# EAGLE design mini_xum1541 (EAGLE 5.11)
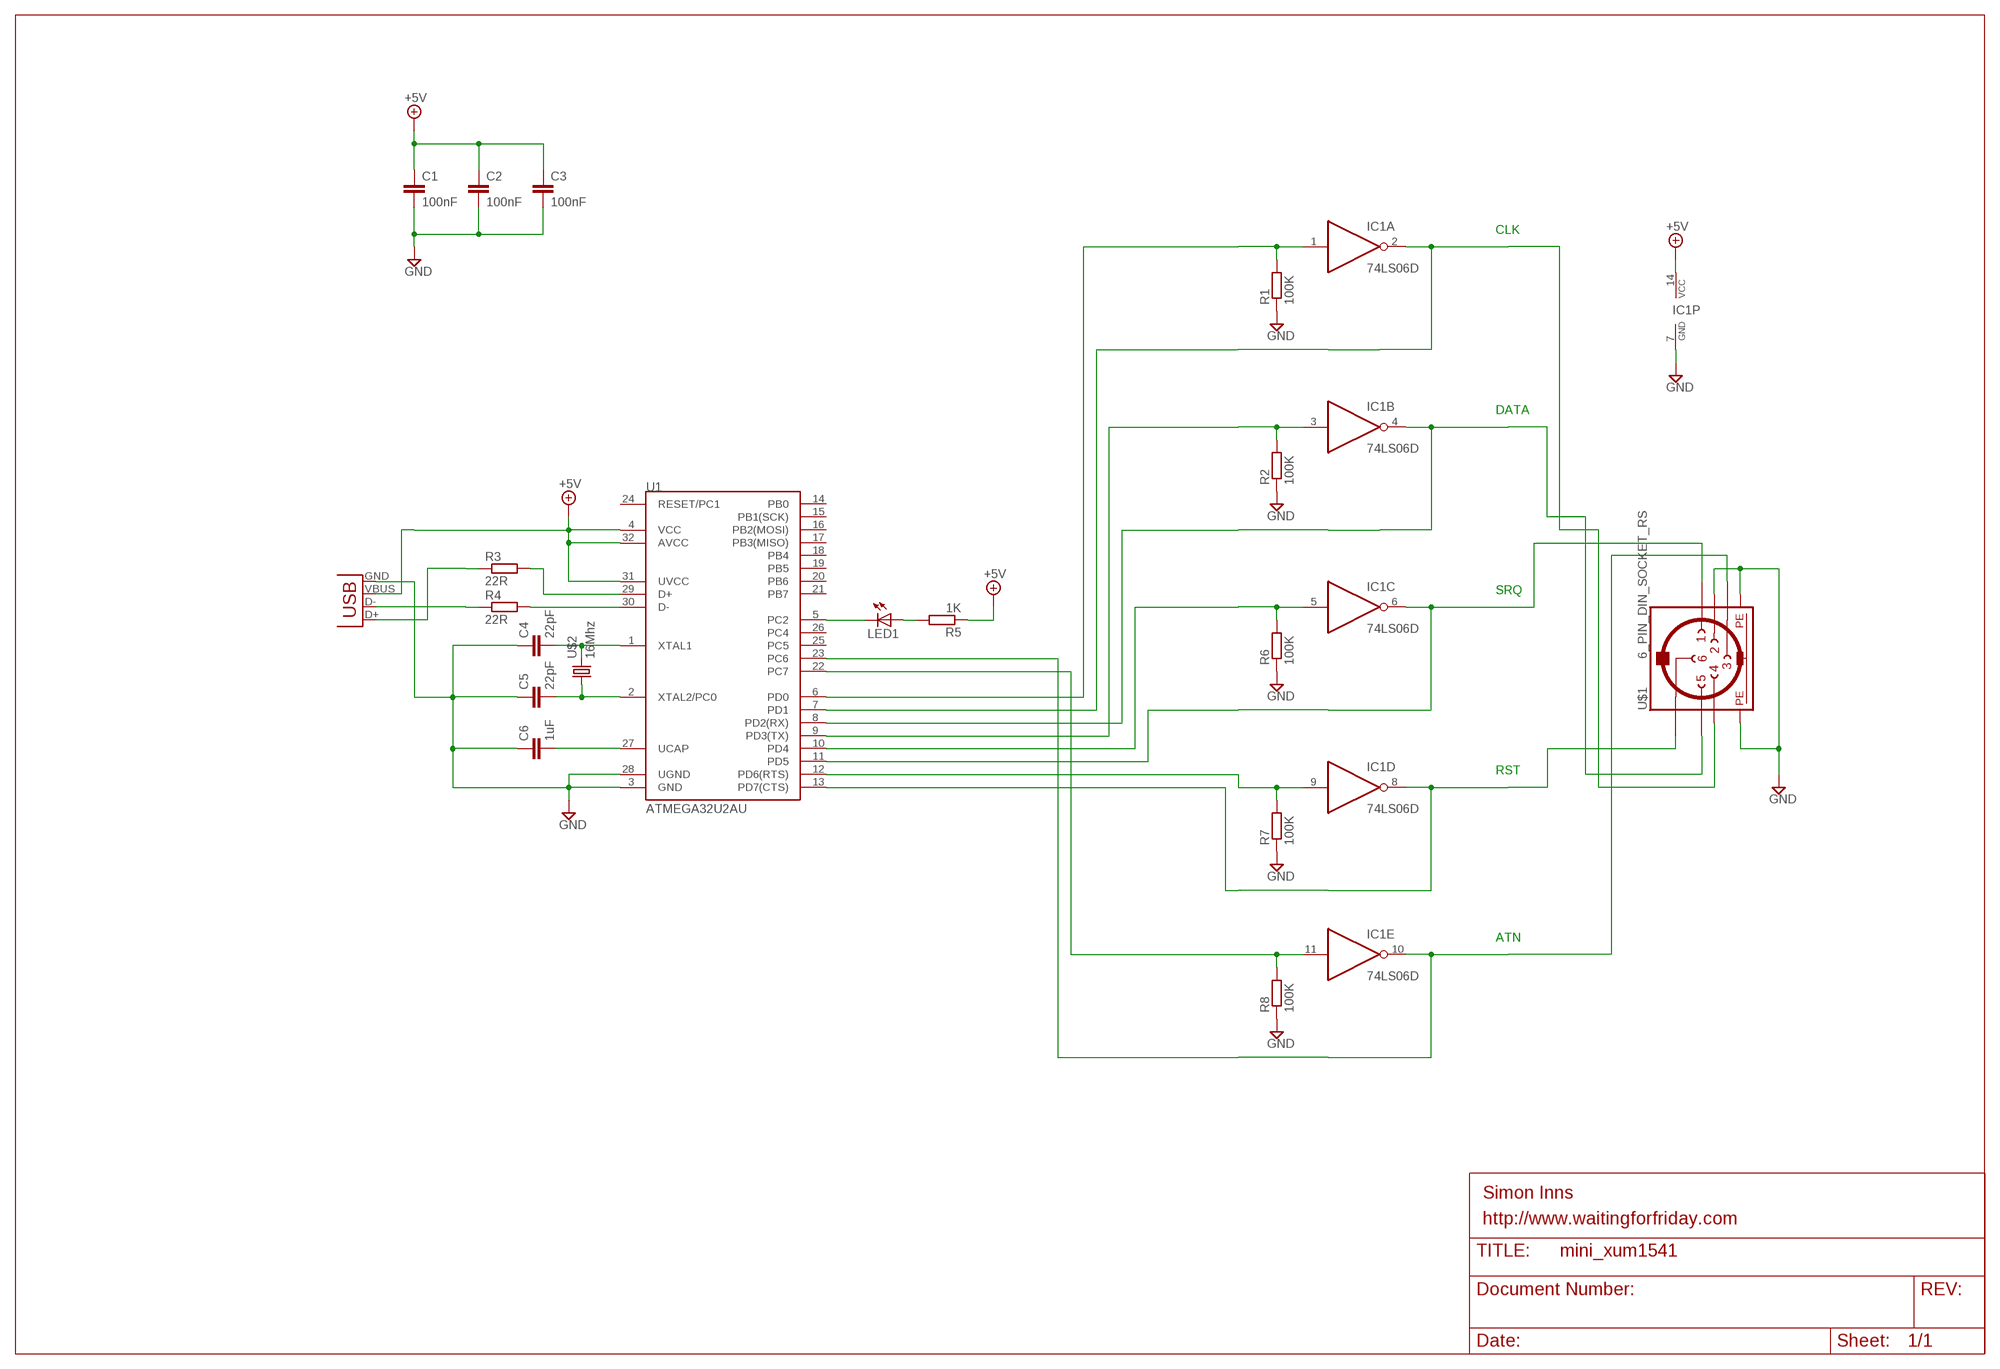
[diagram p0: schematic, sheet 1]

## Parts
C1  100nF  C-EUC0805  [C0805]
C2  100nF  C-EUC0805  [C0805]
C3  100nF  C-EUC0805  [C0805]
C4  22pF  C-EUC0805  [C0805]
C5  22pF  C-EUC0805  [C0805]
C6  1uF  C-EUC0805  [C0805]
IC1  74LS06D  [SO14]
LED1  LED3MM  [LED3MM]
R1  100K  R-EU_M1206  [M1206]
R2  100K  R-EU_M1206  [M1206]
R3  22R  R-EU_M1206  [M1206]
R4  22R  R-EU_M1206  [M1206]
R5  1K  R-EU_M1206  [M1206]
R6  100K  R-EU_M1206  [M1206]
R7  100K  R-EU_M1206  [M1206]
R8  100K  R-EU_M1206  [M1206]
U1  ATMEGA32U2AU  ATMEGA8U2AU  [TQFP32-08]
U$1  6_PIN_DIN_SOCKET_RS  [MAB6H_RS]
U$2  16Mhz  CRYSTAL_SMD3X5MM  [CRYSTAL_SMD_3X5MM]
X1  USBPTH  [USB-B-PTH]

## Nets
+5V: C1.1 C2.1 C3.1 IC1.14(P:VCC) R5.1 U1.4(VCC) U1.31(UVCC) U1.32(AVCC) X1.VBUS
GND: C1.2 C2.2 C3.2 C4.1 C5.1 C6.1 IC1.7(P:GND) R1.1 R2.1 R6.1 R7.1 R8.1 U1.3(GND) U1.28(UGND) U$1.2 U$1.PE U$1.PE@(PE) X1.GND
N$1: IC1.1(A:I) R1.2 U1.6(PD0)
N$3: IC1.2(A:O) U1.7(PD1) U$1.4
N$4: IC1.3(B:I) R2.2 U1.9(PD3(TX))
N$6: IC1.4(B:O) U1.8(PD2(RX)) U$1.5
N$7: IC1.5(C:I) R6.2 U1.10(PD4)
N$9: IC1.6(C:O) U1.11(PD5) U$1.1
N$10: IC1.9(D:I) R7.2 U1.12(PD6(RTS))
N$12: IC1.8(D:O) U1.13(PD7(CTS)) U$1.6
N$13: IC1.11(E:I) R8.2 U1.22(PC7)
N$15: IC1.10(E:O) U1.23(PC6) U$1.3
N$20: C6.2 U1.27(UCAP)
N$21: C5.2 U1.2(XTAL2/PC0) U$2.1
N$22: C4.2 U1.1(XTAL1) U$2.2
N$23: R4.1 X1.D-
N$24: R4.2 U1.30(D-)
N$25: R3.1 X1.D+
N$26: R3.2 U1.29(D+)
N$32: LED1.K(C) U1.5(PC2)
N$33: LED1.A R5.2
Unconnected: IC1.12(F:O) IC1.13(F:I) U1.14(PB0) U1.15(PB1(SCK)) U1.16(PB2(MOSI)) U1.17(PB3(MISO)) U1.18(PB4) U1.19(PB5) U1.20(PB6) U1.21(PB7) U1.24(RESET/PC1) U1.25(PC5) U1.26(PC4)

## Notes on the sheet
- CLK
- DATA
- SRQ
- RST
- ATN
- Simon Inns
- http://www.waitingforfriday.com

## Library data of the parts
C1-C6 = rcl:C-EU: CAPACITOR, European symbol
IC1 = 74xx-eu:74*06: Hex INVERTER, open collector high-voltage output
LED1 = led:LED: LED
R1-R8 = rcl:R-EU_: RESISTOR, European symbol
U1 = SparkFun:ATMEGA8U2: Atmel 8-bit Microcontroller with 8/16/32K Bystes of ISP Flash and USB Controller. ATmega8U2, ATmega16U2, and ATmega32U2
U$1 = simonslbr:6_PIN_DIN_SOCKET_RS: 6 PIN DIN Socket for PCB mounting RS Components part number 491033
U$2 = simonslbr:CRYSTAL_SMD3X5MM: SMD Crystal 3.2mm X 5mm dual pads
X1 = SparkFun:USB: USB Connectors USB-B-PTH is fully proven SKU : PRT-00139 USB-miniB is fully proven SKU : PRT-00587 USB-A-PCB is untested. USB-A-H is throughly reviewed, but untested. Spark Fun Electronics SKU : PRT-00437 USB-B-SMT is throughly reviewed, but untested. Needs silkscreen touching up. USB-A-S has not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

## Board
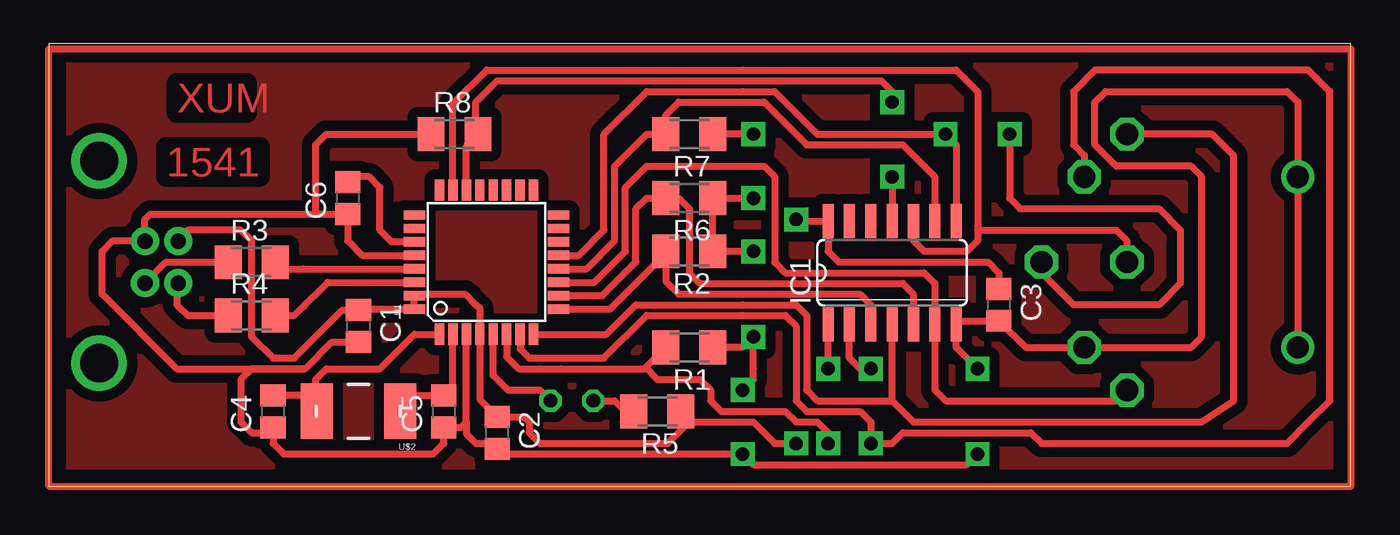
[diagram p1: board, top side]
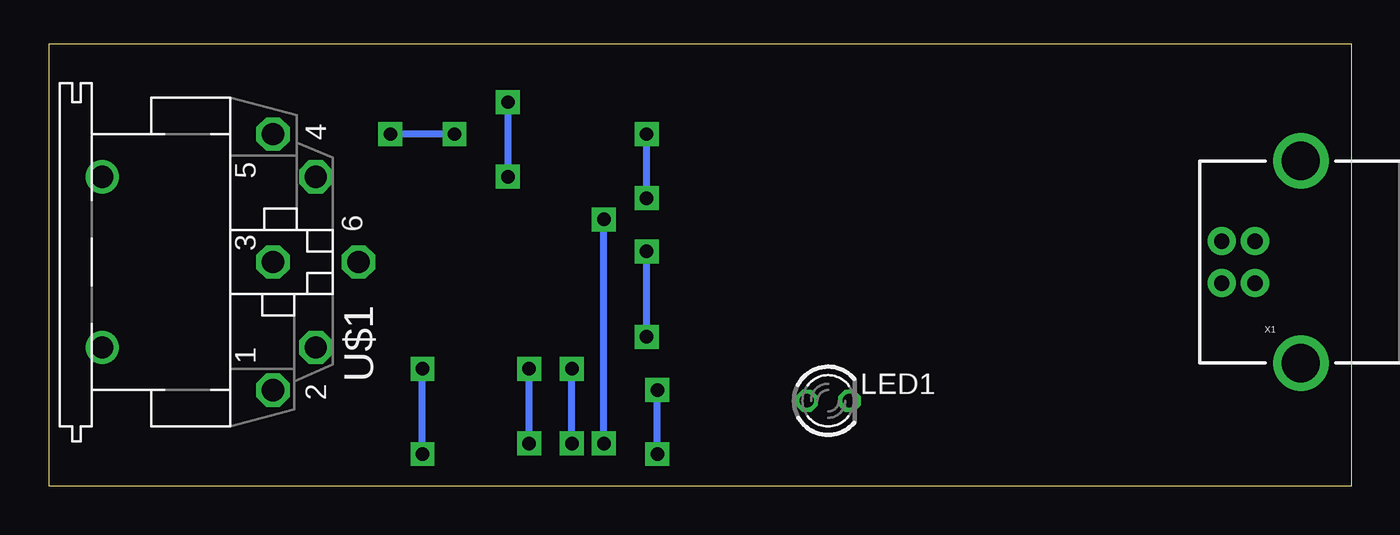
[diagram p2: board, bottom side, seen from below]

Size 77.45 x 26.34 mm. Coordinates in mm from the lower left corner, seen from the top.
Outline: 0,0 77.45,0 77.45,26.34 0,26.34 0,0
Copper layers (1*16): Top 0.035mm / dielectric 1.5mm / Bottom 0.035mm
Design rules "default": minimum track width 10mil, minimum drill 24mil, track to track 8mil, track to pad 8mil, pad to pad 8mil, via to via 8mil, smd to smd 8mil, copper to edge 40mil, drill to drill 8mil, minimum pad ring 10mil, minimum via ring 8mil, stop-mask expansion 4mil, vias tented up to drill 0mil, thermal gap 10mil

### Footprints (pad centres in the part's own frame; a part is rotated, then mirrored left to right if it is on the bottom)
C0805 = smd 1.3 x 1.5: 1 -0.95,0; 2 0.95,0
SO14 = smd 0.66 x 2.032: 1 -3.81,-3.073; 2 -2.54,-3.073; 3 -1.27,-3.073; 4 0,-3.073; 5 1.27,-3.073; 6 2.54,-3.073; 7 3.81,-3.073; 8 3.81,3.073; 9 2.54,3.073; 10 1.27,3.073; 11 0,3.073; 12 -1.27,3.073; 13 -2.54,3.073; 14 -3.81,3.073
LED3MM = drill 0.813 octagon: A -1.27,0; K 1.27,0
M1206 = smd 1.6 x 2: 1 -1.4,0; 2 1.4,0
TQFP32-08 = smd 1.27 x 0.559: 1 -4.293,2.8; 2 -4.293,2; 3 -4.293,1.2; 4 -4.293,0.4; 5 -4.293,-0.4; 6 -4.293,-1.2; 7 -4.293,-2; 8 -4.293,-2.8; 17 4.293,-2.8; 18 4.293,-2; 19 4.293,-1.2; 20 4.293,-0.4; 21 4.293,0.4; 22 4.293,1.2; 23 4.293,2; 24 4.293,2.8 | smd 0.559 x 1.27: 9 -2.8,-4.293; 10 -2,-4.293; 11 -1.2,-4.293; 12 -0.4,-4.293; 13 0.4,-4.293; 14 1.2,-4.293; 15 2,-4.293; 16 2.8,-4.293; 25 2.8,4.293; 26 2,4.293; 27 1.2,4.293; 28 0.4,4.293; 29 -0.4,4.293; 30 -1.2,4.293; 31 -2,4.293; 32 -2.8,4.293
MAB6H_RS = drill 1.321 octagon: 1 7.62,5.08; 2 5.08,7.62; 3 0,5.08; 4 -5.08,7.62; 5 -7.62,5.08; 6 0,10.16 | drill 1.321 round: PE -5.08,-5.08; PE@ 5.08,-5.08
CRYSTAL_SMD_3X5MM = smd 1.9 x 3.302: 1 -2.485,-0.007; 2 2.468,-0.007
USB-B-PTH = drill 0.914 pad 1.676 round: D+ 0,1.25; D- 1.981,1.25; GND 0,-1.25; VBUS 1.981,-1.25 | drill 2.286 round: S1 -2.718,-6.02; S2 -2.718,6.02

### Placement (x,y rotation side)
C1  18.41,9.53 270 top
C2  26.67,3.17 270 top
C3  56.52,10.79 270 top
C4  13.34,4.45 90 top
C5  23.5,4.45 90 top
C6  17.78,17.14 90 top
IC1  50.16,12.7 0 top
LED1  31.11,5.08 0 bottom
R1  38.1,8.26 180 top
R2  38.1,13.97 180 top
R3  12.06,13.34 0 top
R4  12.06,10.16 0 top
R5  36.2,4.45 180 top
R6  38.1,17.14 180 top
R7  38.1,20.95 180 top
R8  24.13,20.95 0 top
U1  ATMEGA16U2AU  [TQFP32-08]  26.04,13.34 90 top
U$1  69.22,13.34 270 bottom
U$2  18.41,4.45 180 top
X1  5.71,13.34 180 bottom

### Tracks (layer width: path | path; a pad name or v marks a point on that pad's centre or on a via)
+5V  (via drill 0.8 pad 1.42)
  Top 0.406: U1.32 U1.31 | U1.32 21.74,11.28 21.59,11.43 24.77,11.43 25.4,10.79 25.64,10.56 U1.4 25.64,5.16 C2.1 28.26,4.12 28.57,3.81 28.57,3.17 29.21,2.54 36.83,2.54 38.1,3.81 | U1.32 18.48,10.54 C1.1 17.46,10.47 14.61,7.62 13.34,7.62 12.06,8.89 12.06,14.61 11.43,15.24 8.26,15.24 7.7,14.68 X1.VBUS | 38.1,3.81 38.1,3.68 R5.1 | C3.1 56.52,12.7 55.88,13.34 46.99,13.34 46.35,13.97 IC1.14 44.55,15.77 v44.45,15.88 | v44.45,2.54 43.18,2.54 41.91,3.81 38.1,3.81
  Bottom 0.406: v44.45,2.54 v44.45,15.88
GND  (via drill 0.8 pad 1.42)
  Top 0.406: 15.88,16.2 6.04,16.2 5.71,15.88 X1.GND 5.7,14.61 3.81,14.61 3.17,13.97 3.17,11.43 7.62,6.99 15.24,6.99 | 15.88,16.2 C6.1 17.78,14.61 18.65,13.73 U1.28 | 24.84,3.81 24.84,3.1 25.4,2.54 26.35,2.54 C2.2 26.99,1.91 28.57,1.91 v41.27,1.91 41.91,1.27 54.61,1.27 v55.24,1.91 | 24.84,3.81 U1.3 | 24.84,3.81 24.52,3.5 C5.1 23.5,2.54 22.86,1.91 13.97,1.91 13.34,2.54 C4.1 13.02,3.17 12.06,3.17 11.43,3.81 11.43,6.35 12.06,6.99 15.24,6.99 | 16.83,8.57 C1.2 16.83,8.57 | 15.24,6.99 16.83,8.57 | 15.24,6.99 16.83,8.57 | R8.1 16.51,20.95 15.88,20.32 15.88,16.2 | v41.91,13.97 R2.1 R6.1 v41.91,17.14 | v41.91,20.95 R7.1 | U$1.PE@ U$1.PE 74.3,22.86 73.66,23.5 62.87,23.5 62.23,22.86 62.23,20.32 63.5,19.05 67.94,19.05 68.58,18.41 68.58,8.89 67.94,8.26 U$1.2 58.1,8.26 C3.2 54.19,9.85 IC1.7 53.98,8.26 v55.24,6.99 | R1.1 41.27,8.26 v41.91,8.89 41.91,6.99 41.91,6.35 v41.27,5.71
  Bottom 0.406: v41.91,8.89 v41.91,13.97 | v41.91,17.14 v41.91,20.95 | v41.27,1.91 v41.27,5.71 | v55.24,1.91 v55.24,6.99
N$1  (via drill 0.8 pad 1.42)
  Top 0.406: U1.6 27.23,7.69 27.94,6.99 29.21,6.99 30.48,6.99 35.43,6.99 35.49,7.05 | 35.49,7.05 R1.2 | v46.35,6.99 IC1.1 | 35.49,7.05 36.2,6.35 37.97,6.35 38.73,6.35 39.37,5.71 39.37,5.08 40.01,4.45 43.81,4.45 44.45,3.81 45.72,3.81 46.35,3.17 v46.35,2.54
  Bottom 0.406: v46.35,2.54 v46.35,6.99
N$2
  Top 0.406: 0,26.04 77.47,26.04 77.47,0 0,0 0,26.04
N$3  (via drill 0.8 pad 1.42)
  Top 0.406: U1.7 28.04,8.16 28.57,7.62 33.02,7.62 35.56,10.16 41.27,10.16 43.81,10.16 44.45,9.53 44.45,5.08 45.09,4.45 48.26,4.45 48.9,3.81 v48.9,2.54 50.16,2.54 50.8,3.17 58.42,3.17 59.05,2.54 73.66,2.54 74.93,3.81 76.2,5.08 76.2,23.5 74.93,24.77 62.23,24.77 60.96,23.5 60.96,20.32 61.59,19.68 U$1.4 | IC1.2 47.62,8.26 47.62,7.62 48.26,6.99 v48.9,6.99
  Bottom 0.406: v48.9,2.54 v48.9,6.99
N$4
  Top 0.406: U1.9 33.4,10.54 36.2,13.34 R2.2 36.7,12.2 37.47,11.43 41.27,11.43 43.18,11.43 44.45,11.43 48.26,11.43 48.9,10.79 IC1.3
N$5
  pour Top (isolate 0.61): 0,26.04 77.47,26.04 77.47,0 0,0
N$6
  Top 0.406: U1.8 33.17,9.04 34.92,10.79 41.27,10.79 44.45,10.79 45.09,10.16 45.09,5.71 45.72,5.08 50.16,5.08 | U$1.5 69.22,20.95 70.48,19.68 70.48,5.08 68.58,3.81 51.44,3.81 50.16,5.08 | 50.16,5.08 IC1.4
N$7
  Top 0.406: U1.10 32.92,11.34 34.92,13.34 34.92,16.51 35.56,17.14 R6.2 37.47,17.14 38.1,16.51 38.1,12.7 38.73,12.06 44.45,12.06 50.8,12.06 51.44,11.43 IC1.5
N$9
  Top 0.406: U1.11 32.45,12.13 34.29,13.97 34.29,17.78 35.56,19.05 39.37,19.05 42.55,19.05 43.18,18.41 43.18,13.34 43.81,12.7 52.07,12.7 52.7,12.06 IC1.6 52.7,6.99 52.7,5.71 53.34,5.08 63.5,5.08 U$1.1
N$10
  Top 0.406: U1.12 31.98,12.94 33.66,14.61 33.66,19.05 35.56,20.95 R7.2 36.7,22.09 37.47,22.86 42.55,22.86 45.09,20.32 50.8,20.32 52.7,18.41 IC1.9
N$12  (via drill 0.8 pad 1.42)
  Top 0.406: U1.13 31.52,13.73 33.02,15.24 33.02,20.95 35.56,23.5 41.27,23.5 43.18,23.5 45.72,20.95 52.7,20.95 v53.34,20.95 53.98,20.32 IC1.8 | U$1.6 59.05,12.7 60.96,10.79 66.04,10.79 67.31,12.06 67.31,15.24 66.04,16.51 57.78,16.51 57.15,17.14 v57.15,20.95
  Bottom 0.406: v53.34,20.95 v57.15,20.95
N$13  (via drill 0.8 pad 1.42)
  Top 0.406: U1.22 24.84,20.26 R8.2 25.4,21.09 25.4,22.86 26.67,24.13 41.27,24.13 49.53,24.13 50.16,23.5 v50.16,22.86 | v50.16,18.41 IC1.11
  Bottom 0.406: v50.16,22.86 v50.16,18.41
N$15
  Top 0.406: U1.23 24.04,22.77 26.04,24.77 41.27,24.77 53.98,24.77 55.24,23.5 55.24,15.24 | 55.24,15.24 55.24,14.61 54.61,13.97 52.07,13.97 51.44,14.61 IC1.10 | U$1.3 64.14,14.61 63.5,15.24 55.24,15.24
N$20
  Top 0.406: U1.27 20.39,14.54 19.68,15.24 19.68,17.78 19.05,18.41 18.1,18.41 C6.2
N$21
  Top 0.406: U$2.1 21.84,5.39 C5.2 24.04,5.93 U1.2
N$22
  Top 0.406: C4.2 15,5.39 U$2.2 15.88,4.52 15.88,6.35 16.51,6.99 19.68,6.99 21.74,9.04 U1.1
N$23
  Top 0.406: R4.1 8.26,10.16 7.62,10.79 7.62,12.01 X1.D-
N$24
  Top 0.406: U1.30 16.58,12.13 14.92,10.48 | 14.92,10.48 14.61,10.16 R4.2 | 14.92,10.48 15.24,10.79
N$25
  Top 0.406: X1.D+ 6.96,13.34 8.26,13.34 R3.1
N$26
  Top 0.406: U1.29 15.13,12.94 13.7,12.94 R3.2
N$32
  Top 0.406: U1.5 26.43,6.58 27.3,5.71 28.57,5.71 29.21,5.71 LED1.K
N$33
  Top 0.406: R5.2 34.16,3.81 34.16,4.58 33.66,5.08 LED1.A

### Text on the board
Top: XUM | 1541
